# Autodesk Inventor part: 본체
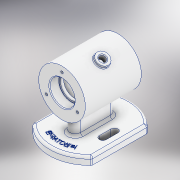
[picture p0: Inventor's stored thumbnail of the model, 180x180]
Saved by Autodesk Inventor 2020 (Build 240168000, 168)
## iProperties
Created: 2022-02
Part Number: 본체
Material: 알루미늄 6061
Document SubType Name: Modeling
Designer: 602-01
Density: 2.7 g/cm^3
Appearance: 알루미늄 - 평지
Mass: 495.269 g
Surface Area: 489.771 cm^2
Volume: 183.433 cm^3
Author: 602-01
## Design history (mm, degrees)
sketch "스케치1"
  geometry: L1 (0, 52)-(0, -52); L2 (-38, 35.496)-(-38, -35.496); L3 (38, -35.496)-(38, 35.496); A1 r 52 centre (0, 0) between (-38, -35.496) and (38, -35.496); A2 r 52 centre (0, 0) between (38, 35.496) and (-38, 35.496); 3 further points
  constraints: 6 end point, 6 point on circle, 3 coincident, 2 centre point, 2 midpoint, 1 horizontal alignment, 1 parallel, 1 vertical
  dimensions: "d1" = 76 distance between parallel lines of L2 L3; "d3" = 38 distance between parallel lines of L1 L3; "d4" = 52 radius of A1
extrude "돌출1" new body sketch "스케치1" distance "d5" = 10; taper "d6" = 0 deg
sketch "스케치2"
  geometry: 1 further point
sketch "스케치3"
  geometry: L1 (62, 36)-(62, -36); L2 (0, 35.496)-(0, -35.496) reference; L3 (62, 36)-(92, 36); L4 (62, -36)-(92, -36); L5 (92, -36)-(92, 36); L6 (78, 36)-(78, 24); L7 (78, 24)-(76, 24); L8 (76, 24)-(76, 20); L9 (76, 20)-(87, 20); L10 (87, 20)-(87, -20); L11 (87, -20)-(76, -20); L12 (76, -20)-(76, -24); L13 (76, -24)-(78, -24); L14 (78, -24)-(78, -36); 5 further points
  constraints: 26 end point, 10 perpendicular, 4 midpoint, 2 horizontal, 2 horizontal alignment, 2 point on line, 1 vertical
  dimensions: "d7" = 62 distance between parallel lines of L2 L1; "d8" = 72 distance of L1.start L1.end; "d9" = 60 diameter of L5 L1; "d10" = 32 diameter of L14 L1; "d11" = 28 diameter of L12 L1; "d12" = 50 diameter of L10 L1; "d13" = 28 diameter of L8 L1; "d14" = 32 diameter of L6 L1; "d15" = 12 distance of L6.start L6.end; "d16" = 12 distance of L13.end L14.end; "d17" = 40 distance of L9.end L10.end
revolve "회전1" sketch "스케치3" stored, may be unused: angle "d18" = 90 deg
sketch "스케치5"
  geometry: L1 (0, -19)-(0, 19); L2 (-7, -19)-(-7, 19); L3 (7, 19)-(7, -19); A1 r 7 centre (0, -19) between (-7, -19) and (7, -19); A2 r 7 centre (0, 19) between (7, 19) and (-7, 19); 1 further point
  constraints: 8 end point, 4 point on circle, 4 tangent, 2 centre point, 1 midpoint, 1 parallel, 1 vertical
  dimensions: "d21" = 14 distance between parallel lines of L3 L2; "d22" = 38 distance of L3.start L3.end
extrude "돌출2" join sketch "스케치5" stored distance "d23" = 10; taper "d24" = 0 deg
sketch "스케치6"
  geometry: L1 (-24, -7.5)-(-24, 7.5); L2 (-28.5, -7.5)-(-28.5, 7.5); L3 (-19.5, 7.5)-(-19.5, -7.5); L4 (24, -7.5)-(24, 7.5); L5 (19.5, -7.5)-(19.5, 7.5); L6 (28.5, 7.5)-(28.5, -7.5); A1 r 4.5 centre (-24, -7.5) between (-28.5, -7.5) and (-19.5, -7.5); A2 r 4.5 centre (-24, 7.5) between (-19.5, 7.5) and (-28.5, 7.5); A3 r 4.5 centre (24, -7.5) between (19.5, -7.5) and (28.5, -7.5); A4 r 4.5 centre (24, 7.5) between (28.5, 7.5) and (19.5, 7.5); 3 further points
  constraints: 16 end point, 8 point on circle, 8 tangent, 4 centre point, 3 parallel, 2 horizontal alignment, 2 midpoint, 1 vertical
  dimensions: "d25" = 24 distance from line of point (0, 0) L1; "d26" = 24 distance from line of L4 point (0, 0); "d27" = 9 distance between parallel lines of L3 L2; "d28" = 9 distance between parallel lines of L6 L5; "d29" = 15 distance of L6.start L6.end; "d30" = 15 distance of L2.start L2.end
extrude "돌출3" cut sketch "스케치6" distance "d31" = 10; taper "d32" = 0 deg
sketch "스케치7"
  geometry: C1 r 16 at (0, 0) reference; 2 further points
  constraints: 1 vertical alignment
  dimensions: "d40" = 23 distance of C1.centre point (0, 23)
hole "구멍1" sketch "스케치7" at (0, 23) diameter "d33" = 3.242; stored, may be unused: countersink angle "d37" = 90 deg, drill point angle "d39" = 120 deg; dims "d34" = 8, "d35" = 4, "d36" = 2, "d38" = 10
chamfer "모따기1" distance "d44" = 1; stored, may be unused: second distance "d45" = 2, angle "d46" = 45 deg
fillet "모깎기1" dims "d47" = 0.3
fillet "모깎기2" dims "d48" = 3
fillet "모깎기3" dims "d49" = 3
fillet "모깎기4" dims "d50" = 3
sketch "스케치12"
  geometry: L1 (-7, 13)-(-7, 30.552) reference; L2 (16.5, 90.579)-(23.428, 86.579); L3 (23.428, 86.579)-(20.428, 81.383); L4 (20.428, 81.383)-(13.5, 85.383); L5 (13.5, 85.383)-(16.5, 90.579); L6 (0, 62)-(13.5, 85.383); L7 (7, 13)-(7, 30.552) reference; 1 further point
  constraints: 10 end point, 2 perpendicular, 1 collinear, 1 parallel
  dimensions: "d88" = 30 deg angle of L7 L6; "d89" = 8 distance of L2.start L2.end; "d90" = 6 distance of L2.end L3.end; "d91" = 33 distance from line of L6.start L2
revolve "회전2" sketch "스케치12" stored, may be unused: angle "d73" = 90 deg
sketch "스케치14"
  geometry: C1 r 42.5 at (0, 0); 1 further point
  constraints: 1 centre point, 1 coincident, 1 other
  dimensions: "d85" = 85 diameter of C1
feature "엠보싱1" sketch "스케치14" dims "d1" = 76, "d3" = 38, "d4" = 52, "d86" = 0.5, "d87" = 0
sketch "스케치15"
  geometry: C1 r 8 at (0, 0) reference; 2 further points
  constraints: 1 coincident
hole "구멍4" sketch "스케치15" at (0, 0) diameter "d92" = 8; stored, may be unused: countersink angle "d96" = 90 deg, drill point angle "d98" = 0 deg; dims "d93" = 8, "d94" = 4, "d95" = 2, "d97" = 11.8
fillet "모깎기6" dims "d99" = 1
node "솔리드1"
pattern_circular "원형 패턴1" dims angle "d42" = 360 deg
mirror "미러1"
feature "A9D066F2-1C7D-4E18-AEED-F7BC21143FA4" dims "d92" = 8, "d93" = 8, "d94" = 4, "d95" = 2, "d96" = 90 deg, "d97" = 11.8, "d98" = 0
other parameters: "d0" = 52, "d68" = 30 deg
